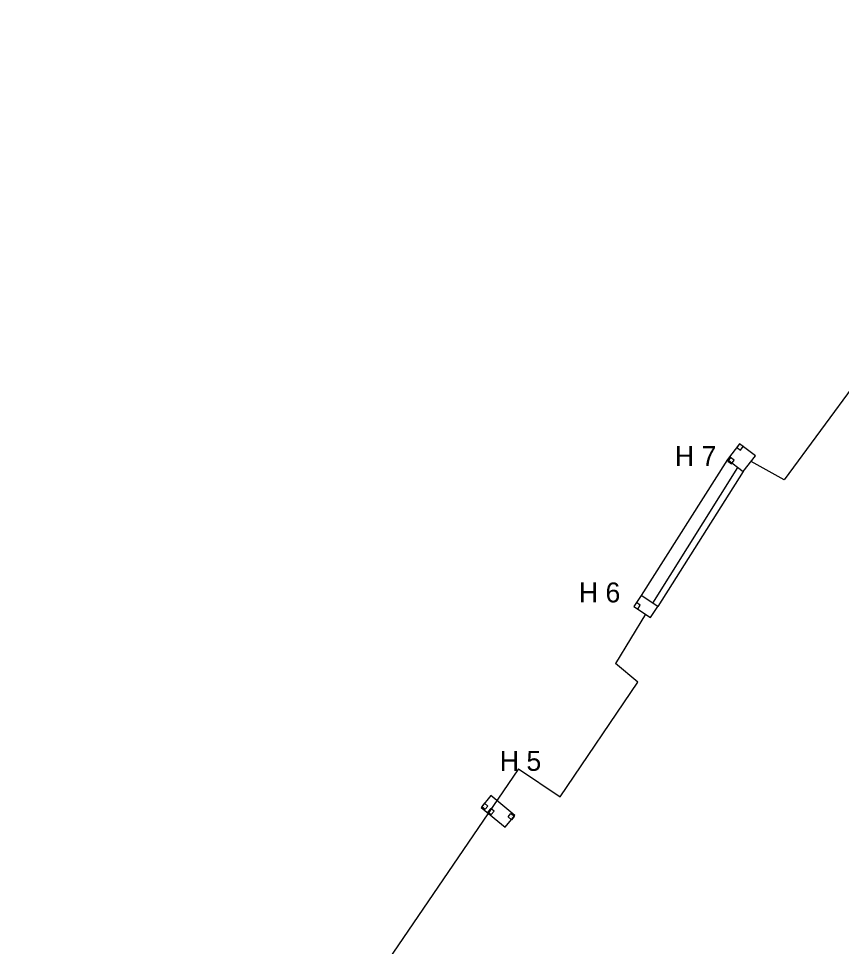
# Model space of a CAD drawing. Extents: x -642943 to -623314, y -1138561 to -1113539.
# Drawn here: x -642485.3 to -642361.3, y -1115211.3 to -1115071.5 of the extents above; entities that cross this region are included whole.
import ezdxf

# ---------------------------------------------------------------- set-up
doc = ezdxf.new("R2010")
doc.units = 0
for name, color, linetype in [('horkovod trasa', 7, 'Continuous'), ('horkovod číslo šachty', 7, 'Continuous'), ('horkovod šachty', 7, 'Continuous')]:
    doc.layers.add(name, color=color, linetype=linetype)

# ---------------------------------------------------------------- blocks, each defined once
blk = doc.blocks.new('POINT_DISPLAY')
blk.add_line((0, 0), (0, 0))

msp = doc.modelspace()

# ---------------------------------------------------------------- linework, layer by layer
at = {"layer": 'horkovod trasa'}
for p, q in [((-642389.76, -1115159.55), (-642376.98, -1115139.08)), ((-642390.88, -1115161.2), (-642395.39, -1115168.61)), ((-642392.01, -1115171.46), (-642395.39, -1115168.61)), ((-642403.71, -1115188.74), (-642392.01, -1115171.46)), ((-642409.99, -1115184.48), (-642485.33, -1115294.93)), ((-642409.99, -1115184.48), (-642403.71, -1115188.74))]:
    msp.add_line(p, q, dxfattribs=at)
msp.add_lwpolyline([(-642332.35, -1115071.45), (-642338.16, -1115078.7), (-642340.05, -1115080.88), (-642331.92, -1115087.66), (-642359.01, -1115126.11), (-642369.97, -1115140.94), (-642374.96, -1115138.17)], dxfattribs=at)
at = {"layer": 'horkovod šachty'}
for p, q in [((-642376.7, -1115135.51), (-642377.12, -1115136.06)), ((-642376.14, -1115135.94), (-642376.7, -1115135.51)), ((-642377.12, -1115136.06), (-642376.57, -1115136.49)), ((-642376.57, -1115136.49), (-642376.14, -1115135.94)), ((-642378.53, -1115137.89), (-642391.5, -1115158.37)), ((-642378.07, -1115137.58), (-642378.47, -1115138.15)), ((-642378.47, -1115138.15), (-642377.9, -1115138.56)), ((-642377.5, -1115137.99), (-642378.07, -1115137.58)), ((-642377.9, -1115138.56), (-642377.5, -1115137.99)), ((-642376.15, -1115139.72), (-642389.02, -1115160.05)), ((-642392.23, -1115159.44), (-642392.62, -1115160.02)), ((-642392.62, -1115160.02), (-642392.04, -1115160.42)), ((-642391.65, -1115159.84), (-642392.23, -1115159.44)), ((-642392.04, -1115160.42), (-642391.65, -1115159.84)), ((-642415.13, -1115189.68), (-642415.55, -1115190.18)), ((-642414.63, -1115190.1), (-642415.13, -1115189.68)), ((-642415.55, -1115190.18), (-642415.05, -1115190.6)), ((-642415.05, -1115190.6), (-642414.63, -1115190.1)), ((-642414.18, -1115190.47), (-642414.6, -1115190.97)), ((-642414.6, -1115190.97), (-642414.1, -1115191.39)), ((-642413.69, -1115190.89), (-642414.18, -1115190.47)), ((-642414.1, -1115191.39), (-642413.69, -1115190.89)), ((-642411.57, -1115191.74), (-642411.15, -1115191.24)), ((-642411.15, -1115191.24), (-642410.66, -1115191.66)), ((-642411.07, -1115192.16), (-642411.57, -1115191.74)), ((-642410.66, -1115191.66), (-642411.07, -1115192.16))]:
    msp.add_line(p, q, dxfattribs=at)
for points in [[(-642374.32, -1115137.33), (-642376.7, -1115135.51), (-642378.53, -1115137.89), (-642376.15, -1115139.72), (-642374.32, -1115137.33)], [(-642392.62, -1115160.02), (-642390.14, -1115161.71), (-642389.02, -1115160.05), (-642391.5, -1115158.37), (-642392.62, -1115160.02)], [(-642414.17, -1115188.53), (-642415.64, -1115190.3), (-642412.03, -1115193.31), (-642410.56, -1115191.54), (-642414.17, -1115188.53)]]:
    msp.add_lwpolyline(points, dxfattribs=at)

# ---------------------------------------------------------------- block references
for p in [(-642376.63, -1115136), (-642377.98, -1115138.07), (-642392.13, -1115159.93), (-642415.08, -1115190.14), (-642414.15, -1115190.93), (-642411.11, -1115191.7)]:
    msp.add_blockref('POINT_DISPLAY', p, dxfattribs=at)

# ---------------------------------------------------------------- texts
at = {"layer": 'horkovod číslo šachty'}
for s, p in [('H 7', (-642386.44, -1115138.87)), ('H 6', (-642400.91, -1115159.42)), ('H 5', (-642412.82, -1115184.8))]:
    msp.add_text(s, height=3, dxfattribs=at).set_placement(p)

doc.saveas('drawing.dxf')
